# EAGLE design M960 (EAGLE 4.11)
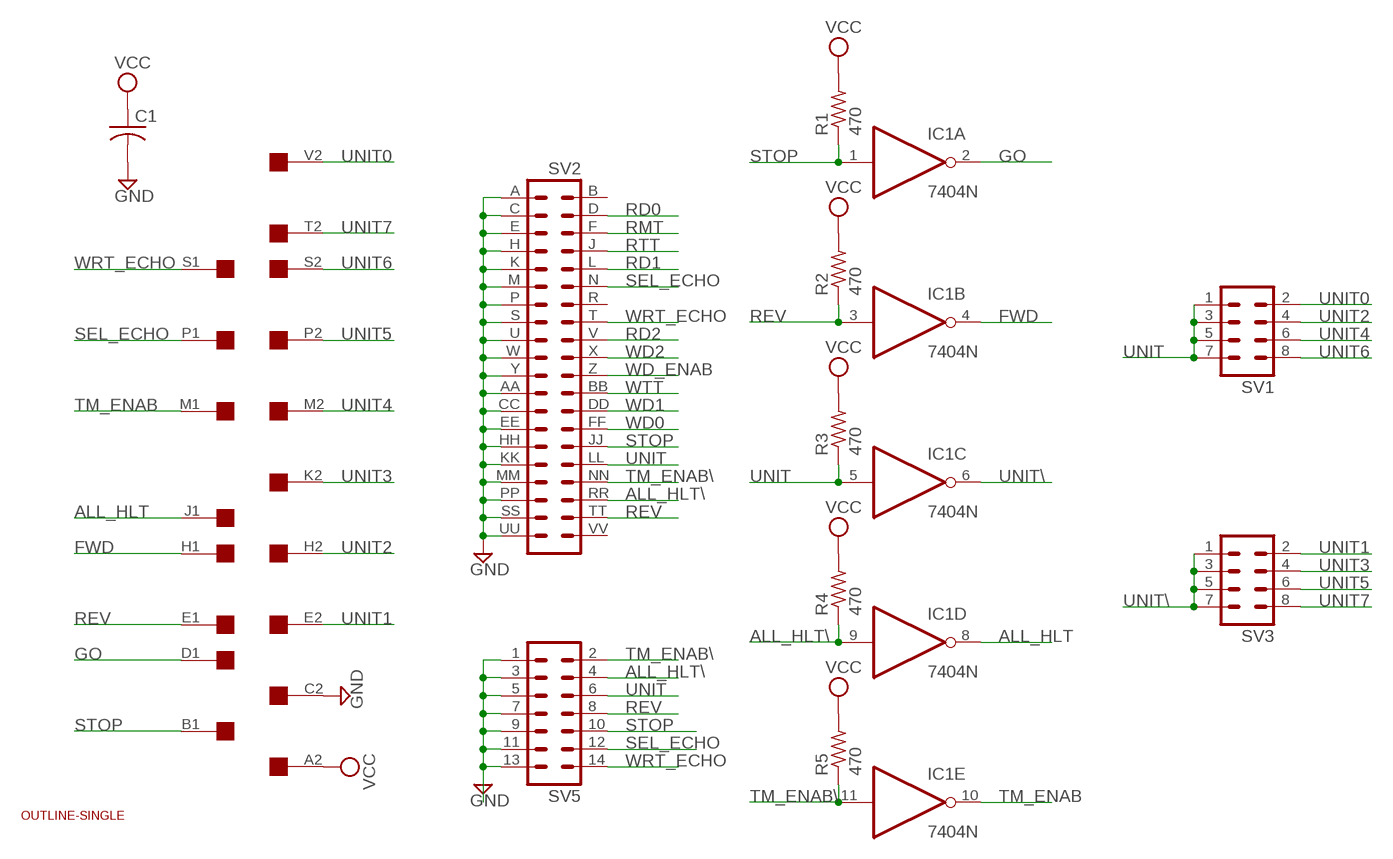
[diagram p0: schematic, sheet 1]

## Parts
C1  C-US050-025X075  [C050-025X075]
IC1  7404N  [DIL14]
R1  470  R-US_0207/10  [0207/10]
R2  470  R-US_0207/10  [0207/10]
R3  470  R-US_0207/10  [0207/10]
R4  470  R-US_0207/10  [0207/10]
R5  470  R-US_0207/10  [0207/10]
SV1  MA04-2  [MA04-2]
SV2  DEC40PIN  [DEC40PIN]
SV3  MA04-2  [MA04-2]
SV5  MA07-2  [MA07-2]
U$1  OUTLINE-SINGLE  [SINGLE]
U$2  SINGLE  [EDGE-CON2]

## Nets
ALL_HLT: IC1.8(D:O) U$2.J1
ALL_HLT\: IC1.9(D:I) R4.1 SV2.RR SV5.4
FWD: IC1.4(B:O) U$2.H1
GND: C1.2 SV2.A SV2.AA SV2.C SV2.CC SV2.E SV2.EE SV2.H SV2.HH SV2.K SV2.KK SV2.M SV2.MM SV2.P SV2.PP SV2.S SV2.SS SV2.U SV2.UU SV2.W SV2.Y SV5.1 SV5.3 SV5.5 SV5.7 SV5.9 SV5.11 SV5.13 U$2.C2
GO: IC1.2(A:O) U$2.D1
RD0: SV2.D
RD1: SV2.L
RD2: SV2.V
REV: IC1.3(B:I) R2.1 SV2.TT SV5.8 U$2.E1
RMT: SV2.F
RTT: SV2.J
SEL_ECHO: SV2.N SV5.12 U$2.P1
STOP: IC1.1(A:I) R1.1 SV2.JJ SV5.10 U$2.B1
TM_ENAB: IC1.10(E:O) U$2.M1
TM_ENAB\: IC1.11(E:I) R5.1 SV2.NN SV5.2
UNIT: IC1.5(C:I) R3.1 SV1.1 SV1.3 SV1.5 SV1.7 SV2.LL SV5.6
UNIT0: SV1.2 U$2.V2
UNIT1: SV3.2 U$2.E2
UNIT2: SV1.4 U$2.H2
UNIT3: SV3.4 U$2.K2
UNIT4: SV1.6 U$2.M2
UNIT5: SV3.6 U$2.P2
UNIT6: SV1.8 U$2.S2
UNIT7: SV3.8 U$2.T2
UNIT\: IC1.6(C:O) SV3.1 SV3.3 SV3.5 SV3.7
VCC: C1.1 R1.2 R2.2 R3.2 R4.2 R5.2 U$2.A2
WD0: SV2.FF
WD1: SV2.DD
WD2: SV2.X
WD_ENAB: SV2.Z
WRT_ECHO: SV2.T SV5.14 U$2.S1
WTT: SV2.BB
Unconnected: IC1.12(F:O) IC1.13(F:I) SV2.B SV2.R SV2.VV U$2.A1 U$2.B2 U$2.C1 U$2.D2 U$2.F1 U$2.F2 U$2.J2 U$2.K1 U$2.L1 U$2.L2 U$2.N1 U$2.N2 U$2.R1 U$2.R2 U$2.T1 U$2.U1 U$2.U2 U$2.V1

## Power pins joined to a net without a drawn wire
GND: IC1.7(P:GND)
VCC: IC1.14(P:VCC)

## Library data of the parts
C1 = rcl:C-US: CAPACITOR, American symbol
IC1 = 74xx-us:74*04: Hex INVERTER
R1-R5 = rcl:R-US_: RESISTOR, American symbol
SV1 SV3 = con-lstb:MA04-2: PIN HEADER
SV2 = dec-con:DEC40PIN: PIN HEADER
SV5 = con-lstb:MA07-2: PIN HEADER
U$1 = dec-con:OUTLINE-*: Board outlines for DEC boards.
U$2 = dec-con:SINGLE: Double-Height DEC board

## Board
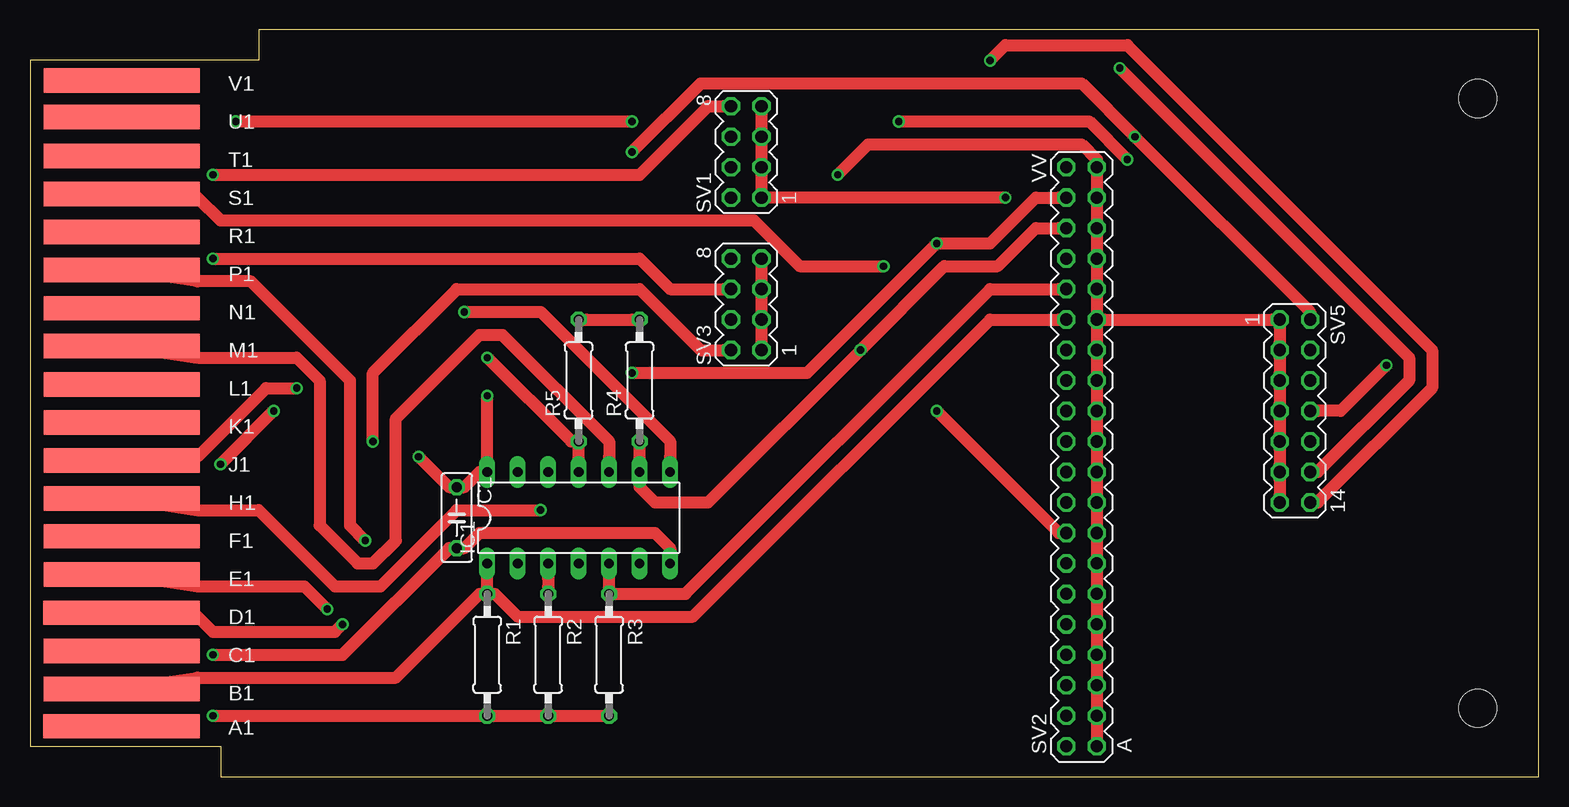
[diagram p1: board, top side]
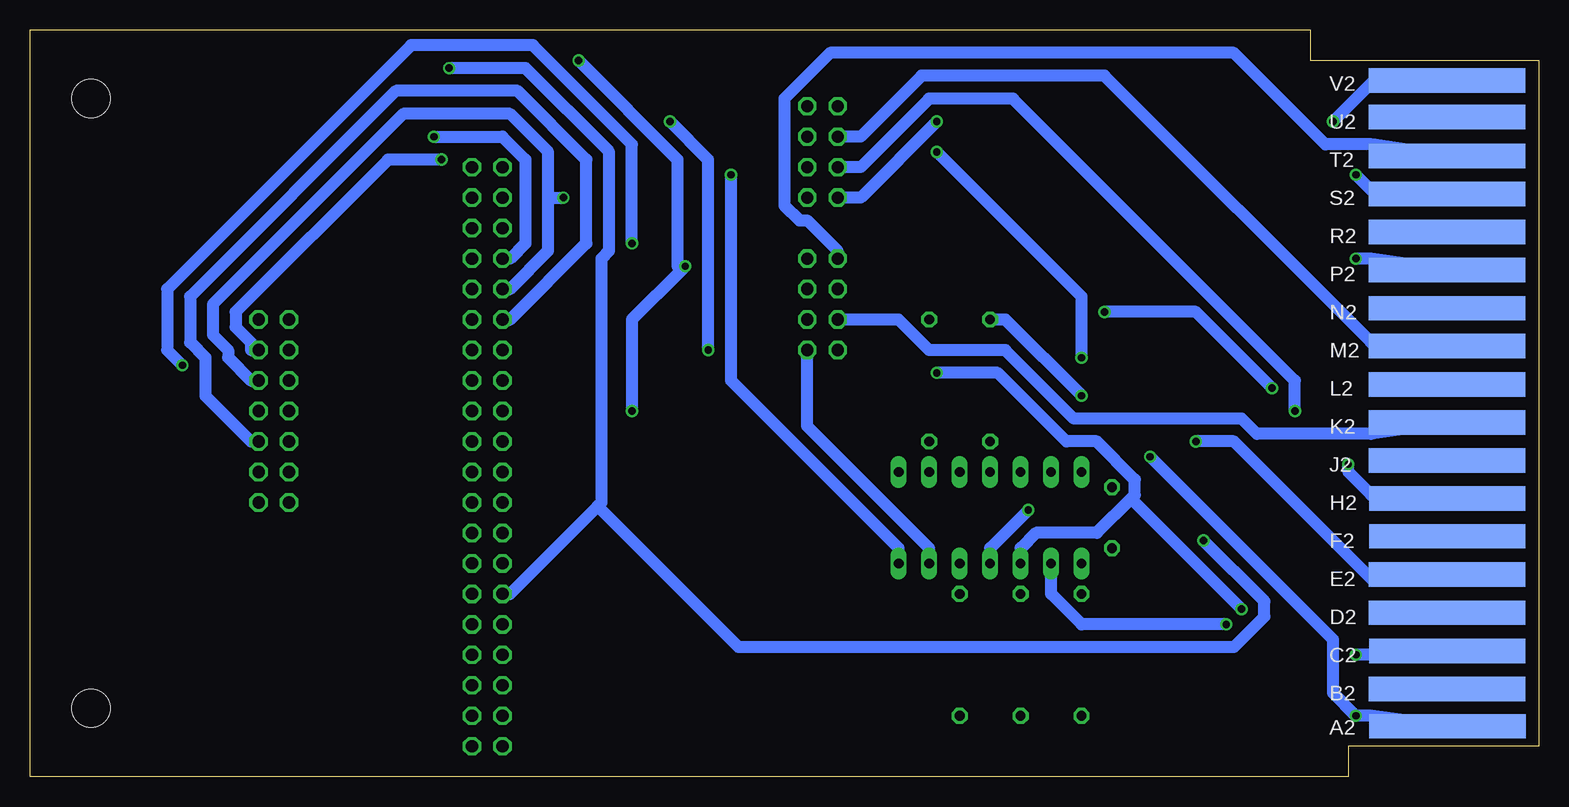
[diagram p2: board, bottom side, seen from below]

Size 125.73 x 62.23 mm. Coordinates in mm from the lower left corner, seen from the top.
Copper layers (1*16): Top 0.035mm / dielectric 1.5mm / Bottom 0.035mm
Design rules "15mils": minimum track width 40mil, minimum drill 24mil, track to track 20mil, track to pad 10mil, pad to pad 10mil, via to via 10mil, smd to smd 10mil, copper to edge 25mil, drill to drill 10mil, minimum pad ring 10mil, minimum via ring 8mil, stop-mask expansion 0mil, vias tented up to drill 0mil, thermal gap 10mil

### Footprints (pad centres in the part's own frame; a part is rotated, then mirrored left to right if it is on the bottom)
C050-025X075 = drill 0.813 octagon: 1 -2.54,0; 2 2.54,0
DIL14 = drill 0.813 long: 1 -7.62,-3.81; 2 -5.08,-3.81; 3 -2.54,-3.81; 4 0,-3.81; 5 2.54,-3.81; 6 5.08,-3.81; 7 7.62,-3.81; 8 7.62,3.81; 9 5.08,3.81; 10 2.54,3.81; 11 0,3.81; 12 -2.54,3.81; 13 -5.08,3.81; 14 -7.62,3.81
0207/10 = drill 0.813 octagon: 1 -5.08,0; 2 5.08,0
MA04-2 = drill 1.016 octagon: 1 -3.81,-1.27; 2 -3.81,1.27; 3 -1.27,-1.27; 4 -1.27,1.27; 5 1.27,-1.27; 6 1.27,1.27; 7 3.81,-1.27; 8 3.81,1.27
DEC40PIN = drill 1.016 octagon: A -24.13,-1.27; AA 3.81,-1.27; B -24.13,1.27; BB 3.81,1.27; C -21.59,-1.27; CC 6.35,-1.27; D -21.59,1.27; DD 6.35,1.27; E -19.05,-1.27; EE 8.89,-1.27; F -19.05,1.27; FF 8.89,1.27; H -16.51,-1.27; HH 11.43,-1.27; J -16.51,1.27; JJ 11.43,1.27; K -13.97,-1.27; KK 13.97,-1.27; L -13.97,1.27; LL 13.97,1.27; M -11.43,-1.27; MM 16.51,-1.27; N -11.43,1.27; NN 16.51,1.27; P -8.89,-1.27; PP 19.05,-1.27; R -8.89,1.27; RR 19.05,1.27; S -6.35,-1.27; SS 21.59,-1.27; T -6.35,1.27; TT 21.59,1.27; U -3.81,-1.27; UU 24.13,-1.27; V -3.81,1.27; VV 24.13,1.27; W -1.27,-1.27; X -1.27,1.27; Y 1.27,-1.27; Z 1.27,1.27
MA07-2 = drill 1.016 octagon: 1 -7.62,-1.27; 2 -7.62,1.27; 3 -5.08,-1.27; 4 -5.08,1.27; 5 -2.54,-1.27; 6 -2.54,1.27; 7 0,-1.27; 8 0,1.27; 9 2.54,-1.27; 10 2.54,1.27; 11 5.08,-1.27; 12 5.08,1.27; 13 7.62,-1.27; 14 7.62,1.27
SINGLE = hole 3.175: 120.65,56.515; 120.65,5.715
EDGE-CON2 = smd 13.017 x 2.032: A1 7.633,4.207; B1 7.639,7.327; C1 7.636,10.489; D1 7.633,13.665; E1 7.642,16.84; F1 7.642,20.041; H1 7.642,23.19; J1 7.642,26.34; K1 7.642,29.515; L1 7.642,32.69; M1 7.642,35.89; N1 7.642,39.04; P1 7.642,42.24; R1 7.642,45.39; S1 7.642,48.565; T1 7.642,51.74; U1 7.642,54.966; V1 7.642,58.026 | smd 13.017 x 2.032 bottom: A2 7.614,4.207; B2 7.642,7.328; C2 7.617,10.49; D2 7.642,13.665; E2 7.642,16.84; F2 7.617,20.041; H2 7.617,23.19; J2 7.642,26.34; K2 7.642,29.515; L2 7.642,32.69; M2 7.642,35.89; N2 7.642,39.04; P2 7.642,42.24; R2 7.642,45.39; S2 7.642,48.565; T2 7.642,51.74; U2 7.642,54.966; V2 7.642,58.026

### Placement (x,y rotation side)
C1  35.56,21.59 270 top
IC1  45.72,21.59 0 top
R1  38.1,10.16 270 top
R2  43.18,10.16 270 top
R3  48.26,10.16 270 top
R4  50.8,33.02 90 top
R5  45.72,33.02 90 top
SV1  59.69,52.07 90 top
SV2  87.63,26.67 90 top
SV3  59.69,39.37 90 top
SV5  105.41,30.48 270 top
U$1  0,0 0 top
U$2  0,0 0 top

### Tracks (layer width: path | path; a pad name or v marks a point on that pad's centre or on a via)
ALL_HLT  (via drill 0.61)
  Top 1.016: v36.2,38.73 42.55,38.73 53.34,27.94 53.34,26.67 IC1.8 | v22.23,32.38 19.69,32.38 13.97,26.67 U$2.J1
  Bottom 1.016: v36.2,38.73 28.58,38.73 v22.23,32.38
ALL_HLT\  (via drill 0.61)
  Top 1.016: R4.1 50.8,27.3 50.8,26.67 IC1.9 50.8,24.13 52.07,22.86 56.52,22.86 v69.22,35.56 76.2,42.55 80.65,42.55 83.82,45.72 85.73,45.72 SV2.RR | v91.44,51.44 88.27,54.61 v72.39,54.61
  Bottom 1.016: v91.44,51.44 95.89,51.44 108.59,38.73 108.59,37.47 107.32,36.2 107.32,35.56 SV5.4 | v72.39,54.61 69.22,51.44 v69.22,35.56
FWD  (via drill 0.61)
  Top 1.016: v42.55,22.23 35.56,22.23 29.21,15.88 25.4,15.88 19.05,22.23 13.97,22.23 U$2.H1
  Bottom 1.016: v42.55,22.23 45.72,19.05 IC1.4
GND  (via drill 0.61)
  Top 1.016: SV5.13 104.14,23.5 104.14,24.77 SV5.11 104.14,26.04 104.14,27.3 SV5.9 104.14,28.57 104.14,29.84 SV5.7 104.14,31.11 104.14,32.38 SV5.5 104.14,33.66 104.14,34.92 SV5.3 104.14,36.2 104.14,37.47 SV5.1 103.51,38.1 89.54,38.1 SV2.HH | SV2.A 88.9,3.17 88.9,4.45 SV2.C 88.9,5.71 88.9,6.99 SV2.E 88.9,8.26 88.9,9.53 SV2.H 88.9,10.79 88.9,12.06 SV2.K 88.9,13.34 88.9,14.61 SV2.M 88.9,15.88 88.9,17.14 SV2.P 88.9,18.41 88.9,19.68 SV2.S 88.9,20.95 88.9,22.23 SV2.U 88.9,23.5 88.9,24.77 SV2.W 88.9,26.04 88.9,27.3 SV2.Y 88.9,28.57 88.9,29.84 SV2.AA 88.9,31.11 88.9,32.38 SV2.CC 88.9,33.66 88.9,34.92 SV2.EE 88.9,36.2 88.9,37.47 SV2.HH | SV2.HH 88.9,38.73 88.9,40.01 SV2.KK 88.9,41.27 88.9,42.55 SV2.MM 88.9,43.81 88.9,45.09 SV2.PP 88.9,46.35 88.9,47.62 SV2.SS 88.9,48.9 88.9,50.16 SV2.UU 88.9,51.44 87.63,52.7 69.85,52.7 v67.31,50.16 | IC1.7 53.34,19.05 52.07,20.32 37.47,20.32 36.2,19.05 C1.2 34.93,19.05 26.04,10.16 v15.24,10.16
  Bottom 1.016: v15.24,10.16 13.97,10.16 U$2.C2 | v67.31,50.16 67.31,33.02 53.34,19.05 IC1.7
GO  (via drill 0.61)
  Top 1.016: v26.04,12.7 25.4,12.06 15.24,12.06 13.97,13.34 U$2.D1
  Bottom 1.016: v26.04,12.7 38.1,12.7 40.64,15.24 40.64,16.51 IC1.2
REV  (via drill 0.61)
  Top 1.016: R2.1 43.18,15.88 43.18,16.51 IC1.3 | v50.17,33.66 64.77,33.66 v75.57,44.45 80.01,44.45 83.82,48.26 85.73,48.26 SV2.TT | v113.03,34.29 109.22,30.48 107.32,30.48 SV5.8 | v24.77,13.97 22.86,15.88 13.97,15.88 U$2.E1
  Bottom 1.016: v50.17,33.66 45.09,33.66 39.37,27.94 36.83,27.94 33.66,24.77 33.66,23.5 33.97,23.18 | 33.97,23.18 36.83,20.32 41.91,20.32 43.18,19.05 IC1.3 | v113.03,34.29 114.3,35.56 114.3,40.64 93.98,60.96 83.82,60.96 75.57,52.7 v75.57,44.45 | v24.77,13.97 33.66,22.86 33.97,23.18
SEL_ECHO  (via drill 0.61)
  Top 1.016: v90.81,59.05 114.94,34.92 114.94,33.02 107.32,25.4 SV5.12 | v27.94,19.68 26.67,20.95 26.67,33.02 18.42,41.27 13.97,41.27 U$2.P1
  Bottom 1.016: 78.42,22.54 78.11,22.86 78.11,43.18 77.47,43.81 77.47,52.07 84.46,59.05 v90.81,59.05 | 78.42,22.54 85.73,15.24 SV2.N | v27.94,19.68 22.86,14.61 22.86,13.34 25.4,10.79 66.68,10.79 78.11,22.23 78.42,22.54
STOP
  Top 1.016: R1.1 38.1,15.88 38.1,16.51 IC1.1 | SV2.JJ 85.73,38.1 80.01,38.1 55.25,13.34 40.64,13.34 38.74,15.24 R1.1 | U$2.B1 13.97,8.26 30.48,8.26 37.47,15.24 R1.1
  Bottom 1.016: SV5.10 107.32,27.94 111.13,31.75 111.13,34.92 112.4,36.2 112.4,40.01 95.25,57.15 85.09,57.15 79.38,51.44 79.38,44.45 85.73,38.1 SV2.JJ
TM_ENAB
  Top 1.016: IC1.10 48.26,26.67 48.26,27.94 39.37,36.83 37.47,36.83 30.48,29.84 30.48,19.68 28.58,17.78 27.31,17.78 24.13,20.95 24.13,33.02 22.23,34.92 13.97,34.92 U$2.M1
TM_ENAB\  (via drill 0.61)
  Top 1.016: IC1.11 45.72,26.67 45.72,27.3 R5.1 45.09,27.94 v38.1,34.92 | SV5.2 106.68,38.73 v92.08,53.34 87.63,57.78 55.88,57.78 v50.17,52.07
  Bottom 1.016: v92.08,53.34 86.36,53.34 84.46,51.44 84.46,44.45 85.73,43.18 SV2.NN | v38.1,34.92 38.1,40.01 v50.17,52.07
UNIT  (via drill 0.61)
  Top 1.016: SV1.7 60.96,55.24 60.96,53.98 SV1.5 60.96,52.7 60.96,51.44 SV1.3 60.96,50.16 60.96,48.9 SV1.1 61.6,48.26 v81.28,48.26 | IC1.5 48.26,16.51 48.26,15.88 R3.1 48.9,15.24 54.61,15.24 80.01,40.64 85.73,40.64 SV2.LL
  Bottom 1.016: 82.55,48.26 82.55,43.81 85.73,40.64 SV2.LL | 82.55,48.26 82.55,52.07 85.73,55.24 94.62,55.24 110.49,39.37 110.49,36.83 109.22,35.56 109.22,34.92 107.32,33.02 SV5.6 | 82.55,48.26 v81.28,48.26
UNIT0  (via drill 0.61)
  Top 1.016: v17.15,54.61 v50.17,54.61
  Bottom 1.016: v50.17,54.61 56.52,48.26 57.79,48.26 SV1.2 | v17.15,54.61 13.97,57.78 U$2.V2
UNIT1  (via drill 0.61)
  Top 1.016: v28.58,27.94 28.58,33.66 35.56,40.64 50.8,40.64 55.88,35.56 57.79,35.56 SV3.2
  Bottom 1.016: v28.58,27.94 25.4,27.94 13.97,16.51 U$2.E2
UNIT2  (via drill 0.61)
  Top 1.016: v15.88,26.04 v20.32,30.48
  Bottom 1.016: v20.32,30.48 20.32,33.02 43.82,56.52 50.8,56.52 56.52,50.8 57.79,50.8 SV1.4 | v15.88,26.04 15.88,25.4 13.97,23.5 U$2.H2
UNIT3
  Bottom 1.016: SV3.4 57.79,38.1 53.34,38.1 50.8,35.56 44.45,35.56 38.74,29.84 24.77,29.84 23.5,28.57 13.97,28.57 U$2.K2
UNIT4
  Bottom 1.016: SV1.6 57.79,53.34 56.52,53.34 51.44,58.42 36.2,58.42 13.97,36.2 U$2.M2
UNIT5  (via drill 0.61)
  Top 1.016: v15.24,43.18 50.8,43.18 53.34,40.64 57.79,40.64 SV3.6
  Bottom 1.016: v15.24,43.18 13.97,43.18 U$2.P2
UNIT6  (via drill 0.61)
  Top 1.016: v15.24,50.16 50.8,50.16 56.52,55.88 57.79,55.88 SV1.8
  Bottom 1.016: v15.24,50.16 13.97,48.9 U$2.S2
UNIT7
  Bottom 1.016: SV3.8 58.42,43.81 60.96,46.35 61.6,46.35 62.87,47.62 62.87,56.52 59.06,60.33 25.4,60.33 17.78,52.7 13.97,52.7 U$2.T2
UNIT\
  Top 1.016: SV3.1 60.96,36.2 60.96,37.47 SV3.3 60.96,38.73 60.96,40.01 SV3.5 60.96,41.27 60.96,42.55 SV3.7
  Bottom 1.016: IC1.6 50.8,19.05 60.96,29.21 60.96,34.92 SV3.1
VCC  (via drill 0.61)
  Top 1.016: R5.2 46.36,38.1 50.17,38.1 R4.2 | v38.1,31.75 38.1,26.67 IC1.14 37.47,25.4 36.2,24.13 C1.1 34.93,24.13 v32.39,26.67 | R3.2 47.63,5.08 43.82,5.08 R2.2 42.55,5.08 38.74,5.08 R1.2 37.47,5.08 v15.24,5.08
  Bottom 1.016: v38.1,31.75 44.45,38.1 45.09,38.1 R5.2 | U$2.A2 13.97,5.08 v15.24,5.08 17.15,6.99 17.15,11.43 v32.39,26.67
WRT_ECHO  (via drill 0.61)
  Top 1.016: v75.57,30.48 85.73,20.32 SV2.T | v71.12,42.55 64.14,42.55 60.33,46.35 15.88,46.35 13.97,48.26 U$2.S1 | v80.01,59.69 81.28,60.96 91.44,60.96 116.84,35.56 116.84,32.38 107.32,22.86 SV5.14
  Bottom 1.016: v75.57,30.48 75.57,38.1 71.44,42.23 | v71.12,42.55 71.44,42.23 | v80.01,59.69 71.76,51.44 71.76,42.55 71.44,42.23

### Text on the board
tValues: Unit7 | Unit5 | Unit3 | Unit1 | Unit6 | Unit4 | Unit2 | Unit0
